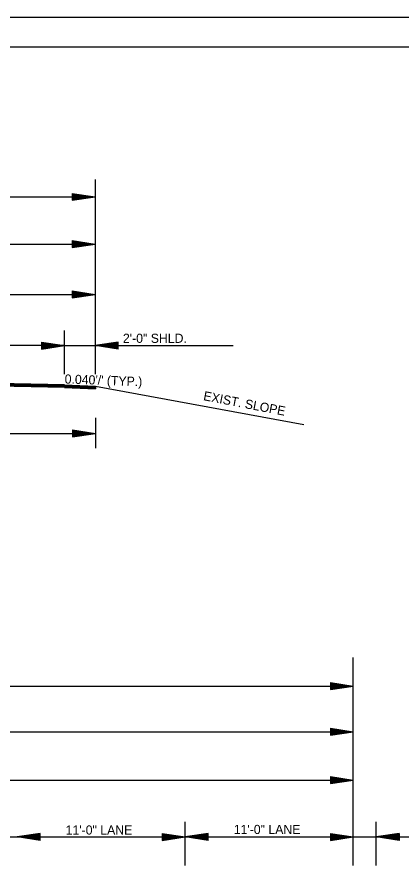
# Model space of a CAD drawing. Extents: x 2263886 to 2266026, y -3122850 to -3121850.
# Drawn here: x 2265782.7 to 2265807.9, y -3122393.1 to -3122337.2 of the extents above; entities that cross this region are included whole.
import ezdxf

# ---------------------------------------------------------------- set-up
doc = ezdxf.new("R2010")
doc.units = 0
for name, color, linetype in [('_CIVIL_CONSTRUCTION', 7, 'Continuous'), ('R_Border Prem', 7, 'Continuous'), ('R_Draft', 7, 'Continuous')]:
    doc.layers.add(name, color=color, linetype=linetype)

msp = doc.modelspace()

# ---------------------------------------------------------------- linework, layer by layer
at = {"layer": '_CIVIL_CONSTRUCTION'}
msp.add_line((2265692.365, -3122337.151), (2265859.032, -3122337.151), dxfattribs=at)
for points in [[(2265692.362, -3122337.151), (2265859.032, -3122337.151), (2265859.032, -3122443.82), (2265692.362, -3122443.82)], [(2265815.526, -3122339.098), (2265815.526, -3122344.038), (2265833.392, -3122344.038), (2265833.392, -3122345.498), (2265844.991, -3122345.498), (2265844.991, -3122357.664), (2265856.656, -3122357.664), (2265856.656, -3122441.828), (2265698.566, -3122441.828), (2265698.566, -3122339.098)]]:
    msp.add_lwpolyline(points, close=True, dxfattribs=at)
at = {"layer": 'R_Border Prem'}
for p, q in [((2265786.306, -3122348.685), (2265787.806, -3122348.91)), ((2265786.306, -3122348.685), (2265786.306, -3122349.135)), ((2265786.306, -3122348.723), (2265787.555, -3122348.91)), ((2265786.306, -3122348.761), (2265787.297, -3122348.91)), ((2265786.306, -3122348.799), (2265787.048, -3122348.91)), ((2265786.306, -3122348.838), (2265786.793, -3122348.91)), ((2265786.306, -3122348.875), (2265786.543, -3122348.91)), ((2265747.761, -3122348.91), (2265787.806, -3122348.91)), ((2265786.306, -3122349.135), (2265787.806, -3122348.91)), ((2265786.306, -3122348.984), (2265786.793, -3122348.91)), ((2265786.306, -3122349.06), (2265787.297, -3122348.91)), ((2265786.306, -3122349.098), (2265787.555, -3122348.91)), ((2265786.306, -3122349.022), (2265787.048, -3122348.91)), ((2265786.306, -3122348.946), (2265786.543, -3122348.91)), ((2265747.761, -3122351.997), (2265787.806, -3122351.997)), ((2265786.306, -3122351.772), (2265787.806, -3122351.997)), ((2265786.306, -3122351.772), (2265786.306, -3122352.222)), ((2265786.306, -3122351.81), (2265787.555, -3122351.997)), ((2265786.306, -3122351.848), (2265787.297, -3122351.997)), ((2265786.306, -3122351.886), (2265787.048, -3122351.997)), ((2265786.306, -3122351.925), (2265786.793, -3122351.997)), ((2265786.306, -3122351.962), (2265786.543, -3122351.997)), ((2265786.306, -3122352.222), (2265787.806, -3122351.997)), ((2265786.306, -3122352.071), (2265786.793, -3122351.997)), ((2265786.306, -3122352.147), (2265787.297, -3122351.997)), ((2265786.306, -3122352.185), (2265787.555, -3122351.997)), ((2265786.306, -3122352.109), (2265787.048, -3122351.997)), ((2265786.306, -3122352.033), (2265786.543, -3122351.997)), ((2265747.761, -3122355.29), (2265787.806, -3122355.29)), ((2265786.306, -3122355.065), (2265787.806, -3122355.29)), ((2265786.306, -3122355.065), (2265786.306, -3122355.515)), ((2265786.306, -3122355.103), (2265787.555, -3122355.29)), ((2265786.306, -3122355.141), (2265787.297, -3122355.29)), ((2265786.306, -3122355.178), (2265787.048, -3122355.29)), ((2265786.306, -3122355.217), (2265786.793, -3122355.29)), ((2265786.306, -3122355.255), (2265786.543, -3122355.29)), ((2265786.306, -3122355.515), (2265787.806, -3122355.29)), ((2265786.306, -3122355.364), (2265786.793, -3122355.29)), ((2265786.306, -3122355.439), (2265787.297, -3122355.29)), ((2265786.306, -3122355.478), (2265787.555, -3122355.29)), ((2265786.306, -3122355.402), (2265787.048, -3122355.29)), ((2265786.306, -3122355.325), (2265786.543, -3122355.29)), ((2265785.806, -3122360.509), (2265785.806, -3122357.654)), ((2265785.806, -3122358.644), (2265773.78, -3122358.644)), ((2265784.306, -3122358.419), (2265785.806, -3122358.644)), ((2265784.306, -3122358.419), (2265784.306, -3122358.869)), ((2265784.306, -3122358.456), (2265785.555, -3122358.644)), ((2265784.306, -3122358.495), (2265785.297, -3122358.644)), ((2265784.306, -3122358.532), (2265785.048, -3122358.644)), ((2265784.306, -3122358.571), (2265784.793, -3122358.644)), ((2265784.306, -3122358.609), (2265784.543, -3122358.644)), ((2265784.306, -3122358.869), (2265785.806, -3122358.644)), ((2265784.306, -3122358.717), (2265784.793, -3122358.644)), ((2265784.306, -3122358.793), (2265785.297, -3122358.644)), ((2265784.306, -3122358.831), (2265785.555, -3122358.644)), ((2265784.306, -3122358.756), (2265785.048, -3122358.644)), ((2265784.306, -3122358.679), (2265784.543, -3122358.644)), ((2265785.806, -3122358.644), (2265796.84, -3122358.644)), ((2265789.306, -3122358.419), (2265787.806, -3122358.644)), ((2265789.306, -3122358.869), (2265787.806, -3122358.644)), ((2265789.306, -3122358.456), (2265788.056, -3122358.644)), ((2265789.306, -3122358.831), (2265788.056, -3122358.644)), ((2265789.306, -3122358.495), (2265788.314, -3122358.644)), ((2265789.306, -3122358.793), (2265788.314, -3122358.644)), ((2265789.306, -3122358.532), (2265788.564, -3122358.644)), ((2265789.306, -3122358.756), (2265788.564, -3122358.644)), ((2265789.306, -3122358.57), (2265788.818, -3122358.644)), ((2265789.306, -3122358.717), (2265788.818, -3122358.644)), ((2265789.306, -3122358.609), (2265789.069, -3122358.644)), ((2265789.306, -3122358.679), (2265789.069, -3122358.644)), ((2265789.306, -3122358.869), (2265789.306, -3122358.419)), ((2265785.803, -3122361.368), (2265767.784, -3122361.008)), ((2265785.802, -3122361.388), (2265767.784, -3122361.028)), ((2265785.804, -3122361.308), (2265767.785, -3122360.948)), ((2265785.803, -3122361.338), (2265767.785, -3122360.978)), ((2265785.805, -3122361.248), (2265767.786, -3122360.888)), ((2265785.805, -3122361.278), (2265767.786, -3122360.918)), ((2265785.806, -3122361.218), (2265767.787, -3122360.858)), ((2265785.799, -3122361.388), (2265787.838, -3122361.47)), ((2265785.8, -3122361.368), (2265787.837, -3122361.45)), ((2265785.801, -3122361.338), (2265787.837, -3122361.42)), ((2265785.802, -3122361.308), (2265787.837, -3122361.39)), ((2265785.803, -3122361.278), (2265787.837, -3122361.359)), ((2265785.805, -3122361.248), (2265787.837, -3122361.329)), ((2265785.806, -3122361.218), (2265787.837, -3122361.299)), ((2265787.837, -3122361.299), (2265787.837, -3122361.469)), ((2265787.837, -3122361.299), (2265787.837, -3122361.469)), ((2265787.837, -3122361.299), (2265801.456, -3122363.801)), ((2265787.837, -3122363.365), (2265787.837, -3122365.365)), ((2265747.756, -3122364.39), (2265787.837, -3122364.39)), ((2265786.337, -3122364.165), (2265787.837, -3122364.39)), ((2265786.337, -3122364.165), (2265786.337, -3122364.615)), ((2265786.337, -3122364.203), (2265787.586, -3122364.39)), ((2265786.337, -3122364.241), (2265787.328, -3122364.39)), ((2265786.337, -3122364.279), (2265787.078, -3122364.39)), ((2265786.337, -3122364.318), (2265786.824, -3122364.39)), ((2265786.337, -3122364.355), (2265786.574, -3122364.39)), ((2265786.337, -3122364.615), (2265787.837, -3122364.39)), ((2265786.337, -3122364.464), (2265786.824, -3122364.39)), ((2265786.337, -3122364.54), (2265787.328, -3122364.39)), ((2265786.337, -3122364.578), (2265787.586, -3122364.39)), ((2265786.337, -3122364.502), (2265787.078, -3122364.39)), ((2265786.337, -3122364.426), (2265786.574, -3122364.39)), ((2265804.699, -3122392.66), (2265804.699, -3122379.051)), ((2265803.199, -3122380.693), (2265804.699, -3122380.918)), ((2265803.199, -3122380.693), (2265803.199, -3122381.143)), ((2265803.199, -3122380.731), (2265804.449, -3122380.918)), ((2265803.199, -3122380.769), (2265804.191, -3122380.918)), ((2265737.699, -3122380.918), (2265804.699, -3122380.918)), ((2265803.199, -3122380.807), (2265803.941, -3122380.918)), ((2265803.199, -3122380.846), (2265803.687, -3122380.918)), ((2265803.199, -3122380.883), (2265803.436, -3122380.918)), ((2265803.199, -3122381.143), (2265804.699, -3122380.918)), ((2265803.199, -3122380.992), (2265803.687, -3122380.918)), ((2265803.199, -3122381.068), (2265804.191, -3122380.918)), ((2265803.199, -3122381.106), (2265804.449, -3122380.918)), ((2265803.199, -3122381.03), (2265803.941, -3122380.918)), ((2265803.199, -3122380.954), (2265803.436, -3122380.918)), ((2265737.699, -3122383.907), (2265804.699, -3122383.907)), ((2265803.199, -3122383.68), (2265804.699, -3122383.905)), ((2265803.199, -3122383.68), (2265803.199, -3122384.13)), ((2265803.199, -3122383.718), (2265804.449, -3122383.905)), ((2265803.199, -3122383.756), (2265804.191, -3122383.905)), ((2265803.199, -3122383.794), (2265803.941, -3122383.905)), ((2265803.199, -3122383.833), (2265803.687, -3122383.905)), ((2265803.199, -3122383.87), (2265803.436, -3122383.905)), ((2265803.199, -3122384.13), (2265804.699, -3122383.905)), ((2265803.199, -3122383.979), (2265803.687, -3122383.905)), ((2265803.199, -3122384.055), (2265804.191, -3122383.905)), ((2265803.199, -3122384.093), (2265804.449, -3122383.905)), ((2265803.199, -3122384.017), (2265803.941, -3122383.905)), ((2265803.199, -3122383.941), (2265803.436, -3122383.905)), ((2265803.199, -3122386.843), (2265804.699, -3122387.068)), ((2265803.199, -3122386.843), (2265803.199, -3122387.293)), ((2265803.199, -3122386.88), (2265804.449, -3122387.068)), ((2265803.199, -3122386.918), (2265804.191, -3122387.068)), ((2265737.699, -3122387.068), (2265804.699, -3122387.068)), ((2265803.199, -3122386.956), (2265803.941, -3122387.068)), ((2265803.199, -3122386.995), (2265803.687, -3122387.068)), ((2265803.199, -3122387.032), (2265803.436, -3122387.068)), ((2265803.199, -3122387.293), (2265804.699, -3122387.068)), ((2265803.199, -3122387.141), (2265803.687, -3122387.068)), ((2265803.199, -3122387.217), (2265804.191, -3122387.068)), ((2265803.199, -3122387.255), (2265804.449, -3122387.068)), ((2265803.199, -3122387.179), (2265803.941, -3122387.068)), ((2265803.199, -3122387.103), (2265803.436, -3122387.068)), ((2265793.699, -3122392.66), (2265793.699, -3122389.805)), ((2265793.699, -3122390.794), (2265793.699, -3122389.805)), ((2265804.699, -3122390.794), (2265804.699, -3122389.805)), ((2265806.2, -3122392.661), (2265806.2, -3122389.806)), ((2265771.699, -3122390.794), (2265782.706, -3122390.794)), ((2265784.206, -3122390.569), (2265782.706, -3122390.794)), ((2265784.206, -3122391.019), (2265782.706, -3122390.794)), ((2265782.706, -3122390.794), (2265793.699, -3122390.794)), ((2265784.206, -3122390.607), (2265782.957, -3122390.794)), ((2265784.206, -3122390.982), (2265782.957, -3122390.794)), ((2265784.206, -3122390.645), (2265783.215, -3122390.794)), ((2265784.206, -3122390.944), (2265783.215, -3122390.794)), ((2265784.206, -3122390.683), (2265783.465, -3122390.794)), ((2265784.206, -3122390.906), (2265783.465, -3122390.794)), ((2265784.206, -3122390.721), (2265783.719, -3122390.794)), ((2265784.206, -3122390.867), (2265783.719, -3122390.794)), ((2265784.206, -3122390.759), (2265783.969, -3122390.794)), ((2265784.206, -3122390.83), (2265783.969, -3122390.794)), ((2265784.206, -3122391.019), (2265784.206, -3122390.569)), ((2265792.199, -3122390.569), (2265793.699, -3122390.794)), ((2265792.199, -3122390.569), (2265792.199, -3122391.019)), ((2265792.199, -3122390.607), (2265793.449, -3122390.794)), ((2265792.199, -3122390.645), (2265793.191, -3122390.794)), ((2265792.199, -3122390.683), (2265792.941, -3122390.794)), ((2265792.199, -3122390.722), (2265792.687, -3122390.794)), ((2265792.199, -3122390.759), (2265792.436, -3122390.794)), ((2265792.199, -3122391.019), (2265793.699, -3122390.794)), ((2265792.199, -3122390.868), (2265792.687, -3122390.794)), ((2265792.199, -3122390.944), (2265793.191, -3122390.794)), ((2265792.199, -3122390.982), (2265793.449, -3122390.794)), ((2265792.199, -3122390.906), (2265792.941, -3122390.794)), ((2265792.199, -3122390.83), (2265792.436, -3122390.794)), ((2265795.199, -3122390.569), (2265793.699, -3122390.794)), ((2265793.699, -3122390.794), (2265804.699, -3122390.794)), ((2265795.199, -3122391.019), (2265793.699, -3122390.794)), ((2265795.199, -3122390.607), (2265793.95, -3122390.794)), ((2265795.199, -3122390.982), (2265793.95, -3122390.794)), ((2265795.199, -3122390.645), (2265794.208, -3122390.794)), ((2265795.199, -3122390.944), (2265794.208, -3122390.794)), ((2265795.199, -3122390.683), (2265794.457, -3122390.794)), ((2265795.199, -3122390.906), (2265794.457, -3122390.794)), ((2265795.199, -3122390.721), (2265794.712, -3122390.794)), ((2265795.199, -3122390.867), (2265794.712, -3122390.794)), ((2265795.199, -3122390.759), (2265794.962, -3122390.794)), ((2265795.199, -3122390.83), (2265794.962, -3122390.794)), ((2265795.199, -3122391.019), (2265795.199, -3122390.569)), ((2265803.199, -3122390.569), (2265804.699, -3122390.794)), ((2265803.199, -3122390.569), (2265803.199, -3122391.019)), ((2265803.199, -3122390.607), (2265804.449, -3122390.794)), ((2265803.199, -3122390.645), (2265804.191, -3122390.794)), ((2265803.199, -3122390.683), (2265803.941, -3122390.794)), ((2265803.199, -3122390.722), (2265803.687, -3122390.794)), ((2265803.199, -3122390.759), (2265803.436, -3122390.794)), ((2265803.199, -3122391.019), (2265804.699, -3122390.794)), ((2265803.199, -3122390.868), (2265803.687, -3122390.794)), ((2265803.199, -3122390.944), (2265804.191, -3122390.794)), ((2265803.199, -3122390.982), (2265804.449, -3122390.794)), ((2265803.199, -3122390.906), (2265803.941, -3122390.794)), ((2265803.199, -3122390.83), (2265803.436, -3122390.794)), ((2265804.699, -3122390.794), (2265815.258, -3122390.794)), ((2265807.7, -3122390.57), (2265806.2, -3122390.795)), ((2265807.7, -3122391.02), (2265806.2, -3122390.795)), ((2265807.7, -3122390.607), (2265806.45, -3122390.795)), ((2265807.7, -3122390.982), (2265806.45, -3122390.795)), ((2265807.7, -3122390.646), (2265806.708, -3122390.795)), ((2265807.7, -3122390.944), (2265806.708, -3122390.795)), ((2265807.7, -3122390.683), (2265806.958, -3122390.795)), ((2265807.7, -3122390.907), (2265806.958, -3122390.795)), ((2265807.7, -3122390.722), (2265807.212, -3122390.795)), ((2265807.7, -3122390.868), (2265807.212, -3122390.795)), ((2265807.7, -3122390.76), (2265807.463, -3122390.795)), ((2265807.7, -3122390.83), (2265807.463, -3122390.795)), ((2265807.7, -3122390.57), (2265807.7, -3122391.02))]:
    msp.add_line(p, q, dxfattribs=at)
msp.add_lwpolyline([(2265787.806, -3122347.784), (2265787.806, -3122360.509)], dxfattribs=at)
at = {"layer": 'R_Draft'}
msp.add_line((2265698.566, -3122339.098), (2265856.656, -3122339.098), dxfattribs=at)

# ---------------------------------------------------------------- texts
at = {"layer": 'R_Border Prem'}
for s, p in [('2\'-0" SHLD.', (2265789.626, -3122358.465)), ('11\'-0" LANE', (2265785.877, -3122390.638)), ('11\'-0" LANE', (2265796.877, -3122390.601))]:
    msp.add_text(s, height=0.6, dxfattribs=at).set_placement(p)
for s, rotation, p in [("0.040'/' (TYP.)", 358.0196, (2265785.807, -3122361.124)), ('EXIST. SLOPE', 349.1171, (2265794.852, -3122362.208))]:
    msp.add_text(s, height=0.6, rotation=rotation, dxfattribs=at).set_placement(p)

doc.saveas('drawing.dxf')
